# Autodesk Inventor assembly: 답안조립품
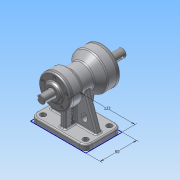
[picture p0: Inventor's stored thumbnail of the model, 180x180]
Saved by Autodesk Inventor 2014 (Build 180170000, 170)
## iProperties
Created: 2015-08
Part Number: 답안조립품
Document SubType Name: Assembly
Designer: study
Author: study
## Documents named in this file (10)
- C:\Users\study\Desktop\450805V1025\답안조립품.iam
- C:\Users\study\Desktop\450805V1025\1-본체.ipt
- C:\Users\study\Desktop\450805V1025\베어링 6205.ipt
- C:\Users\study\Desktop\450805V1025\앞커버.ipt
- C:\Users\study\Desktop\450805V1025\오일실 .ipt
- 오일실 .ipt
- C:\Users\study\Desktop\450805V1025\축.ipt
- C:\Users\study\Desktop\450805V1025\베어링 6203.ipt
- C:\Users\study\Desktop\450805V1025\뒤커버.ipt
- C:\Users\study\Desktop\450805V1025\M4x0.5.ipt
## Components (11 placed, 2 different names)
1. 1-본체:1
2. M4x0.5:2
3. M4x0.5:3
4. M4x0.5:4
5. M4x0.5:5
6. M4x0.5:6
7. M4x0.5:1
8. M4x0.5:7
9. M4x0.5:8
10. M4x0.5:9
11. M4x0.5:10
